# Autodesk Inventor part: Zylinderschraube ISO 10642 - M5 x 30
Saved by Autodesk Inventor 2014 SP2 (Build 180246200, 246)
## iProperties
Created: 2015-07
Part Number: Zylinderschraube ISO 10642 - M5 x 30
Material: Generisch
Document SubType Name: Modeling
Designer: e_krauts
Density: 1 g/cm^3
Appearance: Vorgabe
Author: e_krauts
Sending System: SolidWorks 2011
Last Author: e_boekem
Sachnummer: IS0 10642 M5x30
Einheit: Stck.
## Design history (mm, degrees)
node "Zylinderschraube ISO 10642 - M5 x 30.ipt1"
node "Hex"
node "Basis1"
